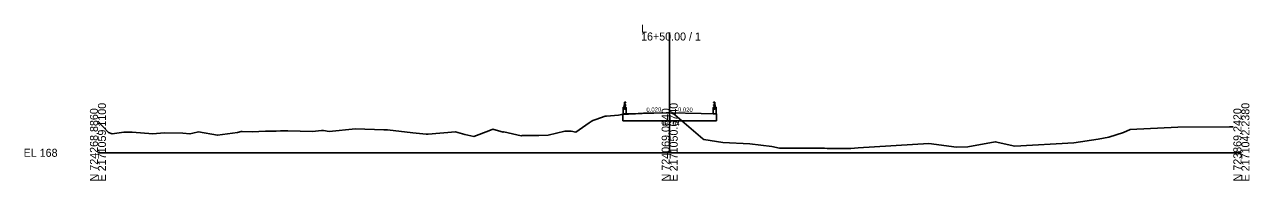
# Model space of a CAD drawing. Extents: x -26 to 2803, y -10 to 9553.
# Drawn here: x -25.7 to 402.8, y 8990.3 to 9044.9 of the extents above; entities that cross this region are included whole.
import ezdxf

# ---------------------------------------------------------------- set-up
doc = ezdxf.new("R2010")
doc.units = 0
for name, color, linetype in [('Exist Cross Section Cell', 7, 'Continuous'), ('Exist XS Center Line Elevation Label', 7, 'Continuous'), ('Exist XS Ground Line', 7, 'Continuous'), ('Prop XS Bridge', 7, 'Continuous'), ('Prop XS Dump Level', 7, 'Continuous'), ('Prop XS SE Text', 7, 'Continuous')]:
    doc.layers.add(name, color=color, linetype=linetype)

msp = doc.modelspace()

# ---------------------------------------------------------------- linework, layer by layer
at = {"layer": 'Exist Cross Section Cell'}
for p, q in [((200, 9000), (200, 9042.09)), ((0, 9000), (200, 9000)), ((200, 9000), (400, 9000))]:
    msp.add_line(p, q, dxfattribs=at)
at = {"layer": 'Exist XS Ground Line'}
msp.add_lwpolyline([(0, 9011.05), (3.69, 9007.06), (5, 9006.6), (9.03, 9007.27), (11.93, 9007.24), (19.24, 9006.62), (23.12, 9006.96), (29.69, 9006.9), (32.17, 9006.59), (33.16, 9006.86), (35.17, 9007.29), (41.79, 9006.14), (48.79, 9007.15), (50.06, 9007.4), (50.46, 9007.4), (53.98, 9007.38), (58.63, 9007.55), (62.31, 9007.62), (63.91, 9007.64), (65.19, 9007.66), (66.45, 9007.66), (75.05, 9007.43), (78.24, 9007.83), (78.86, 9007.75), (80.84, 9007.43), (90.15, 9008.34), (100, 9008.03), (101.29, 9008.02), (110.11, 9007.03), (114.79, 9006.52), (115.56, 9006.53), (125.09, 9007.31), (128.3, 9006.39), (131.55, 9005.76), (136.72, 9007.69), (138.09, 9008.22), (141.7, 9007.24), (141.97, 9007.29), (148.05, 9005.99), (148.39, 9006.01), (154.22, 9006.08), (157.47, 9006.13), (163.38, 9007.55), (165.56, 9007.54), (167.18, 9007.27), (171.89, 9010.51), (172.54, 9011), (173.13, 9011.25), (174.14, 9011.6), (177.42, 9012.84), (177.85, 9012.81), (182.16, 9013.18), (183.21, 9013.44), (190.4, 9013.78), (190.85, 9013.85), (198.83, 9014.03), (200, 9013.94), (200.81, 9013.88), (201.58, 9013.56), (201.79, 9013.27), (211.57, 9004.94), (211.92, 9004.66), (218.59, 9003.59), (228.02, 9003.15), (235.75, 9002.18), (238.48, 9001.61), (248.27, 9001.62), (254.12, 9001.58), (255.06, 9001.53), (263.38, 9001.47), (265.92, 9001.78), (290.67, 9003.3), (300.31, 9001.96), (304.25, 9002.06), (313.87, 9003.88), (320.71, 9002.37), (341.44, 9003.54), (349.87, 9004.82), (353.68, 9005.47), (358.78, 9007.05), (361.12, 9008.2), (377.78, 9008.97), (395.82, 9009.05), (397.1, 9009.06)], dxfattribs=at)
at = {"layer": 'Prop XS Bridge'}
for p, q in [((184.19, 9017.72), (184.07, 9016)), ((184.19, 9017.72), (184.3, 9017.75)), ((184.19, 9015.96), (184.19, 9017.72)), ((184.19, 9016.9), (184.19, 9016.9)), ((184.37, 9017.75), (184.3, 9017.75)), ((184.3, 9015.96), (184.3, 9017.75)), ((184.37, 9015.96), (184.37, 9017.75)), ((184.43, 9017.72), (184.43, 9017.63)), ((184.43, 9017.53), (184.43, 9017.63)), ((184.43, 9016.79), (184.43, 9016.69)), ((184.43, 9016.59), (184.43, 9016.69)), ((215.57, 9017.72), (215.57, 9017.63)), ((215.57, 9017.53), (215.57, 9017.63)), ((215.57, 9016.79), (215.57, 9016.69)), ((215.57, 9016.59), (215.57, 9016.69)), ((215.63, 9017.75), (215.7, 9017.75)), ((215.63, 9015.96), (215.63, 9017.75)), ((215.81, 9017.72), (215.7, 9017.75)), ((215.7, 9015.96), (215.7, 9017.75)), ((215.81, 9015.96), (215.81, 9017.72)), ((215.81, 9017.72), (215.93, 9016)), ((215.81, 9016.9), (215.81, 9016.9)), ((183.57, 9013.6), (183.62, 9013.66)), ((183.57, 9013.6), (183.57, 9011.15)), ((183.7, 9013.66), (183.62, 9013.66)), ((183.69, 9015.88), (183.73, 9015.93)), ((183.69, 9015.88), (183.69, 9013.66)), ((184.75, 9013.66), (183.7, 9013.66)), ((184.7, 9015.93), (183.73, 9015.93)), ((184.07, 9016.02), (184.07, 9016.05)), ((184.07, 9015.96), (184.07, 9016)), ((184.2, 9015.89), (184.11, 9015.89)), ((184.2, 9015.88), (184.11, 9015.88)), ((184.15, 9015.85), (184.11, 9015.85)), ((184.15, 9015.84), (184.11, 9015.84)), ((184.15, 9015.81), (184.11, 9015.81)), ((184.15, 9015.8), (184.11, 9015.8)), ((184.15, 9015.77), (184.11, 9015.77)), ((184.15, 9015.76), (184.11, 9015.76)), ((184.15, 9015.73), (184.11, 9015.73)), ((184.15, 9015.72), (184.11, 9015.72)), ((184.15, 9015.87), (184.13, 9015.87)), ((184.15, 9015.86), (184.13, 9015.86)), ((184.15, 9015.83), (184.13, 9015.83)), ((184.15, 9015.82), (184.13, 9015.82)), ((184.15, 9015.79), (184.13, 9015.79)), ((184.15, 9015.78), (184.13, 9015.78)), ((184.15, 9015.75), (184.13, 9015.75)), ((184.15, 9015.74), (184.13, 9015.74)), ((184.18, 9016.04), (184.14, 9016.04)), ((184.14, 9016.04), (184.14, 9016)), ((184.14, 9015.89), (184.14, 9015.96)), ((184.16, 9015.87), (184.15, 9015.87)), ((184.15, 9015.87), (184.15, 9015.37)), ((184.18, 9015.87), (184.16, 9015.87)), ((184.16, 9015.87), (184.16, 9015.37)), ((184.18, 9015.86), (184.16, 9015.86)), ((184.2, 9015.85), (184.16, 9015.85)), ((184.2, 9015.84), (184.16, 9015.84)), ((184.18, 9015.83), (184.16, 9015.83)), ((184.18, 9015.82), (184.16, 9015.82)), ((184.2, 9015.81), (184.16, 9015.81)), ((184.2, 9015.8), (184.16, 9015.8)), ((184.18, 9015.79), (184.16, 9015.79)), ((184.18, 9015.78), (184.16, 9015.78)), ((184.2, 9015.77), (184.16, 9015.77)), ((184.2, 9015.76), (184.16, 9015.76)), ((184.18, 9015.75), (184.16, 9015.75)), ((184.18, 9015.74), (184.16, 9015.74)), ((184.2, 9015.73), (184.16, 9015.73)), ((184.2, 9015.72), (184.16, 9015.72)), ((184.18, 9016), (184.18, 9016.04)), ((184.18, 9015.89), (184.18, 9015.96)), ((184.43, 9015.32), (184.21, 9015.32)), ((184.43, 9015.3), (184.21, 9015.3)), ((184.53, 9015.89), (184.44, 9015.89)), ((184.53, 9015.88), (184.44, 9015.88)), ((184.48, 9015.85), (184.44, 9015.85)), ((184.48, 9015.84), (184.44, 9015.84)), ((184.48, 9015.81), (184.44, 9015.81)), ((184.48, 9015.8), (184.44, 9015.8)), ((184.48, 9015.77), (184.44, 9015.77)), ((184.48, 9015.76), (184.44, 9015.76)), ((184.48, 9015.73), (184.44, 9015.73)), ((184.48, 9015.72), (184.44, 9015.72)), ((184.48, 9015.87), (184.46, 9015.87)), ((184.48, 9015.86), (184.46, 9015.86)), ((184.48, 9015.83), (184.46, 9015.83)), ((184.48, 9015.82), (184.46, 9015.82)), ((184.48, 9015.79), (184.46, 9015.79)), ((184.48, 9015.78), (184.46, 9015.78)), ((184.48, 9015.75), (184.46, 9015.75)), ((184.48, 9015.74), (184.46, 9015.74)), ((184.51, 9016.05), (184.47, 9016.05)), ((184.47, 9016.05), (184.47, 9016.01)), ((184.47, 9015.89), (184.47, 9015.97)), ((184.49, 9015.87), (184.48, 9015.87)), ((184.48, 9015.87), (184.48, 9015.37)), ((184.51, 9015.87), (184.49, 9015.87)), ((184.49, 9015.87), (184.49, 9015.37)), ((184.51, 9015.86), (184.49, 9015.86)), ((184.53, 9015.85), (184.49, 9015.85)), ((184.53, 9015.84), (184.49, 9015.84)), ((184.51, 9015.83), (184.49, 9015.83)), ((184.51, 9015.82), (184.49, 9015.82)), ((184.53, 9015.81), (184.49, 9015.81)), ((184.53, 9015.8), (184.49, 9015.8)), ((184.51, 9015.79), (184.49, 9015.79)), ((184.51, 9015.78), (184.49, 9015.78)), ((184.53, 9015.77), (184.49, 9015.77)), ((184.53, 9015.76), (184.49, 9015.76)), ((184.51, 9015.75), (184.49, 9015.75)), ((184.51, 9015.74), (184.49, 9015.74)), ((184.53, 9015.73), (184.49, 9015.73)), ((184.53, 9015.72), (184.49, 9015.72)), ((184.51, 9016.01), (184.51, 9016.05)), ((184.51, 9015.89), (184.51, 9015.97)), ((184.7, 9015.93), (184.75, 9015.88)), ((184.75, 9015.88), (184.75, 9013.66)), ((189, 9013.74), (184.75, 9013.66)), ((189, 9013.74), (200, 9013.96)), ((200, 9013.96), (211, 9013.74)), ((211, 9013.74), (215.25, 9013.66)), ((215.25, 9015.88), (215.3, 9015.93)), ((215.25, 9015.88), (215.25, 9013.66)), ((215.25, 9013.66), (216.3, 9013.66)), ((215.3, 9015.93), (216.27, 9015.93)), ((215.47, 9015.89), (215.56, 9015.89)), ((215.47, 9015.88), (215.56, 9015.88)), ((215.47, 9015.85), (215.51, 9015.85)), ((215.47, 9015.84), (215.51, 9015.84)), ((215.47, 9015.81), (215.51, 9015.81)), ((215.47, 9015.8), (215.51, 9015.8)), ((215.47, 9015.77), (215.51, 9015.77)), ((215.47, 9015.76), (215.51, 9015.76)), ((215.47, 9015.73), (215.51, 9015.73)), ((215.47, 9015.72), (215.51, 9015.72)), ((215.49, 9016.01), (215.49, 9016.05)), ((215.49, 9016.05), (215.53, 9016.05)), ((215.49, 9015.89), (215.49, 9015.97)), ((215.49, 9015.87), (215.51, 9015.87)), ((215.49, 9015.86), (215.51, 9015.86)), ((215.49, 9015.83), (215.51, 9015.83)), ((215.49, 9015.82), (215.51, 9015.82)), ((215.49, 9015.79), (215.51, 9015.79)), ((215.49, 9015.78), (215.51, 9015.78)), ((215.49, 9015.75), (215.51, 9015.75)), ((215.49, 9015.74), (215.51, 9015.74)), ((215.51, 9015.87), (215.52, 9015.87)), ((215.51, 9015.87), (215.51, 9015.37)), ((215.52, 9015.87), (215.54, 9015.87)), ((215.52, 9015.87), (215.52, 9015.37)), ((215.52, 9015.86), (215.54, 9015.86)), ((215.52, 9015.85), (215.56, 9015.85)), ((215.52, 9015.84), (215.56, 9015.84)), ((215.52, 9015.83), (215.54, 9015.83)), ((215.52, 9015.82), (215.54, 9015.82)), ((215.52, 9015.81), (215.56, 9015.81)), ((215.52, 9015.8), (215.56, 9015.8)), ((215.52, 9015.79), (215.54, 9015.79)), ((215.52, 9015.78), (215.54, 9015.78)), ((215.52, 9015.77), (215.56, 9015.77)), ((215.52, 9015.76), (215.56, 9015.76)), ((215.52, 9015.75), (215.54, 9015.75)), ((215.52, 9015.74), (215.54, 9015.74)), ((215.52, 9015.73), (215.56, 9015.73)), ((215.52, 9015.72), (215.56, 9015.72)), ((215.53, 9016.05), (215.53, 9016.01)), ((215.53, 9015.89), (215.53, 9015.97)), ((215.57, 9015.32), (215.79, 9015.32)), ((215.57, 9015.3), (215.79, 9015.3)), ((215.8, 9015.89), (215.89, 9015.89)), ((215.8, 9015.88), (215.89, 9015.88)), ((215.8, 9015.85), (215.84, 9015.85)), ((215.8, 9015.84), (215.84, 9015.84)), ((215.8, 9015.81), (215.84, 9015.81)), ((215.8, 9015.8), (215.84, 9015.8)), ((215.8, 9015.77), (215.84, 9015.77)), ((215.8, 9015.76), (215.84, 9015.76)), ((215.8, 9015.73), (215.84, 9015.73)), ((215.8, 9015.72), (215.84, 9015.72)), ((215.82, 9016), (215.82, 9016.04)), ((215.82, 9016.04), (215.86, 9016.04)), ((215.82, 9015.89), (215.82, 9015.96)), ((215.82, 9015.87), (215.84, 9015.87)), ((215.82, 9015.86), (215.84, 9015.86)), ((215.82, 9015.83), (215.84, 9015.83)), ((215.82, 9015.82), (215.84, 9015.82)), ((215.82, 9015.79), (215.84, 9015.79)), ((215.82, 9015.78), (215.84, 9015.78)), ((215.82, 9015.75), (215.84, 9015.75)), ((215.82, 9015.74), (215.84, 9015.74)), ((215.84, 9015.87), (215.85, 9015.87)), ((215.84, 9015.87), (215.84, 9015.37)), ((215.85, 9015.87), (215.87, 9015.87)), ((215.85, 9015.87), (215.85, 9015.37)), ((215.85, 9015.86), (215.87, 9015.86)), ((215.85, 9015.85), (215.89, 9015.85)), ((215.85, 9015.84), (215.89, 9015.84)), ((215.85, 9015.83), (215.87, 9015.83)), ((215.85, 9015.82), (215.87, 9015.82)), ((215.85, 9015.81), (215.89, 9015.81)), ((215.85, 9015.8), (215.89, 9015.8)), ((215.85, 9015.79), (215.87, 9015.79)), ((215.85, 9015.78), (215.87, 9015.78)), ((215.85, 9015.77), (215.89, 9015.77)), ((215.85, 9015.76), (215.89, 9015.76)), ((215.85, 9015.75), (215.87, 9015.75)), ((215.85, 9015.74), (215.87, 9015.74)), ((215.85, 9015.73), (215.89, 9015.73)), ((215.85, 9015.72), (215.89, 9015.72)), ((215.86, 9016.04), (215.86, 9016)), ((215.86, 9015.89), (215.86, 9015.96)), ((215.93, 9016.02), (215.93, 9016.05)), ((215.93, 9015.96), (215.93, 9016)), ((216.27, 9015.93), (216.31, 9015.88)), ((216.3, 9013.66), (216.38, 9013.66)), ((216.31, 9015.88), (216.31, 9013.66)), ((216.43, 9013.6), (216.38, 9013.66)), ((216.43, 9013.6), (216.43, 9011.15)), ((216.43, 9011.15), (183.57, 9011.15))]:
    msp.add_line(p, q, dxfattribs=at)
for points in [[(184.55, 9015.93), (184.55, 9015.97), (184.39, 9015.97), (184.39, 9016.34), (184.37, 9016.34), (184.37, 9015.96), (184.07, 9015.96), (184.07, 9015.99), (184.07, 9015.99), (184.07, 9015.93), (184.21, 9015.93), (184.21, 9015.95), (184.35, 9015.95), (184.35, 9015.93), (184.55, 9015.93)], [(184.37, 9017.5), (184.37, 9017.55), (184.39, 9017.55), (184.39, 9017.54), (184.39, 9017.54), (184.39, 9017.52), (184.42, 9017.52), (184.42, 9017.55), (184.42, 9017.63), (184.42, 9017.7), (184.42, 9017.73), (184.39, 9017.73), (184.39, 9017.71), (184.39, 9017.71), (184.39, 9017.7), (184.37, 9017.7), (184.37, 9017.75)], [(184.37, 9016.57), (184.37, 9016.61), (184.39, 9016.61), (184.39, 9016.6), (184.39, 9016.6), (184.39, 9016.58), (184.42, 9016.58), (184.42, 9016.61), (184.42, 9016.69), (184.42, 9016.76), (184.42, 9016.79), (184.39, 9016.79), (184.39, 9016.77), (184.39, 9016.77), (184.39, 9016.77), (184.37, 9016.77), (184.37, 9016.81)], [(215.45, 9015.93), (215.45, 9015.97), (215.61, 9015.97), (215.61, 9016.34), (215.63, 9016.34), (215.63, 9015.96), (215.93, 9015.96), (215.93, 9015.99), (215.93, 9015.99), (215.93, 9015.93), (215.79, 9015.93), (215.79, 9015.95), (215.65, 9015.95), (215.65, 9015.93), (215.45, 9015.93)], [(215.63, 9017.5), (215.63, 9017.55), (215.61, 9017.55), (215.61, 9017.54), (215.61, 9017.54), (215.61, 9017.52), (215.58, 9017.52), (215.58, 9017.55), (215.58, 9017.63), (215.58, 9017.7), (215.58, 9017.73), (215.61, 9017.73), (215.61, 9017.71), (215.61, 9017.71), (215.61, 9017.7), (215.63, 9017.7), (215.63, 9017.75)], [(215.63, 9016.57), (215.63, 9016.61), (215.61, 9016.61), (215.61, 9016.6), (215.61, 9016.6), (215.61, 9016.58), (215.58, 9016.58), (215.58, 9016.61), (215.58, 9016.69), (215.58, 9016.76), (215.58, 9016.79), (215.61, 9016.79), (215.61, 9016.77), (215.61, 9016.77), (215.61, 9016.77), (215.63, 9016.77), (215.63, 9016.81)], [(184.11, 9015.89), (184.11, 9015.88), (184.13, 9015.87), (184.13, 9015.86), (184.11, 9015.85), (184.11, 9015.84), (184.13, 9015.83), (184.13, 9015.82), (184.11, 9015.81), (184.11, 9015.8), (184.13, 9015.79), (184.13, 9015.78), (184.11, 9015.77), (184.11, 9015.76), (184.13, 9015.75), (184.13, 9015.74), (184.11, 9015.73), (184.11, 9015.72)], [(184.2, 9015.96), (184.2, 9015.97), (184.16, 9015.97), (184.12, 9015.97), (184.12, 9015.96)], [(184.19, 9015.97), (184.19, 9016), (184.18, 9016), (184.13, 9016), (184.13, 9016), (184.13, 9015.97), (184.19, 9015.97), (184.17, 9015.97), (184.17, 9016), (184.17, 9016), (184.17, 9016), (184.16, 9016), (184.15, 9016), (184.15, 9016), (184.15, 9015.97), (184.15, 9016), (184.14, 9016)], [(184.2, 9015.89), (184.2, 9015.88), (184.18, 9015.87), (184.18, 9015.86), (184.2, 9015.85), (184.2, 9015.84), (184.18, 9015.83), (184.18, 9015.82), (184.2, 9015.81), (184.2, 9015.8), (184.18, 9015.79), (184.18, 9015.78), (184.2, 9015.77), (184.2, 9015.76), (184.18, 9015.75), (184.18, 9015.74), (184.2, 9015.73), (184.2, 9015.72)], [(184.44, 9015.89), (184.44, 9015.88), (184.46, 9015.87), (184.46, 9015.86), (184.44, 9015.85), (184.44, 9015.84), (184.46, 9015.83), (184.46, 9015.82), (184.44, 9015.81), (184.44, 9015.8), (184.46, 9015.79), (184.46, 9015.78), (184.44, 9015.77), (184.44, 9015.76), (184.46, 9015.75), (184.46, 9015.74), (184.44, 9015.73), (184.44, 9015.72)], [(184.53, 9015.97), (184.53, 9015.98), (184.49, 9015.98), (184.45, 9015.98), (184.45, 9015.97)], [(184.52, 9015.98), (184.52, 9016.01), (184.51, 9016.01), (184.46, 9016.01), (184.46, 9016.01), (184.46, 9015.98), (184.52, 9015.98), (184.5, 9015.98), (184.5, 9016.01), (184.5, 9016.01), (184.5, 9016.01), (184.49, 9016.01), (184.48, 9016.01), (184.48, 9016.01), (184.48, 9015.98), (184.48, 9016.01), (184.47, 9016.01)], [(184.53, 9015.89), (184.53, 9015.88), (184.51, 9015.87), (184.51, 9015.86), (184.53, 9015.85), (184.53, 9015.84), (184.51, 9015.83), (184.51, 9015.82), (184.53, 9015.81), (184.53, 9015.8), (184.51, 9015.79), (184.51, 9015.78), (184.53, 9015.77), (184.53, 9015.76), (184.51, 9015.75), (184.51, 9015.74), (184.53, 9015.73), (184.53, 9015.72)], [(215.47, 9015.97), (215.47, 9015.98), (215.51, 9015.98), (215.55, 9015.98), (215.55, 9015.97)], [(215.47, 9015.89), (215.47, 9015.88), (215.49, 9015.87), (215.49, 9015.86), (215.47, 9015.85), (215.47, 9015.84), (215.49, 9015.83), (215.49, 9015.82), (215.47, 9015.81), (215.47, 9015.8), (215.49, 9015.79), (215.49, 9015.78), (215.47, 9015.77), (215.47, 9015.76), (215.49, 9015.75), (215.49, 9015.74), (215.47, 9015.73), (215.47, 9015.72)], [(215.48, 9015.98), (215.48, 9016.01), (215.49, 9016.01), (215.54, 9016.01), (215.54, 9016.01), (215.54, 9015.98), (215.48, 9015.98), (215.5, 9015.98), (215.5, 9016.01), (215.5, 9016.01), (215.5, 9016.01), (215.51, 9016.01), (215.52, 9016.01), (215.52, 9016.01), (215.52, 9015.98), (215.52, 9016.01), (215.53, 9016.01)], [(215.56, 9015.89), (215.56, 9015.88), (215.54, 9015.87), (215.54, 9015.86), (215.56, 9015.85), (215.56, 9015.84), (215.54, 9015.83), (215.54, 9015.82), (215.56, 9015.81), (215.56, 9015.8), (215.54, 9015.79), (215.54, 9015.78), (215.56, 9015.77), (215.56, 9015.76), (215.54, 9015.75), (215.54, 9015.74), (215.56, 9015.73), (215.56, 9015.72)], [(215.8, 9015.96), (215.8, 9015.97), (215.84, 9015.97), (215.88, 9015.97), (215.88, 9015.96)], [(215.8, 9015.89), (215.8, 9015.88), (215.82, 9015.87), (215.82, 9015.86), (215.8, 9015.85), (215.8, 9015.84), (215.82, 9015.83), (215.82, 9015.82), (215.8, 9015.81), (215.8, 9015.8), (215.82, 9015.79), (215.82, 9015.78), (215.8, 9015.77), (215.8, 9015.76), (215.82, 9015.75), (215.82, 9015.74), (215.8, 9015.73), (215.8, 9015.72)], [(215.81, 9015.97), (215.81, 9016), (215.82, 9016), (215.87, 9016), (215.87, 9016), (215.87, 9015.97), (215.81, 9015.97), (215.83, 9015.97), (215.83, 9016), (215.83, 9016), (215.83, 9016), (215.84, 9016), (215.85, 9016), (215.85, 9016), (215.85, 9015.97), (215.85, 9016), (215.86, 9016)], [(215.89, 9015.89), (215.89, 9015.88), (215.87, 9015.87), (215.87, 9015.86), (215.89, 9015.85), (215.89, 9015.84), (215.87, 9015.83), (215.87, 9015.82), (215.89, 9015.81), (215.89, 9015.8), (215.87, 9015.79), (215.87, 9015.78), (215.89, 9015.77), (215.89, 9015.76), (215.87, 9015.75), (215.87, 9015.74), (215.89, 9015.73), (215.89, 9015.72)]]:
    msp.add_lwpolyline(points, dxfattribs=at)
for centre in [(184.12, 9015.74), (184.53, 9015.74), (215.47, 9015.74), (215.88, 9015.74)]:
    msp.add_circle(centre, 0.00793, dxfattribs=at)
for centre, radius, start, end in [((184.44, 9017.72), 0.00744, 90, 180), ((184.44, 9017.53), 0.00744, 180, 270), ((184.44, 9016.79), 0.00744, 90, 180), ((184.44, 9016.59), 0.00744, 180, 270), ((215.56, 9017.72), 0.00744, 0, 90), ((215.56, 9017.53), 0.00744, 270, 360), ((215.56, 9016.79), 0.00744, 0, 90), ((215.56, 9016.59), 0.00744, 270, 360), ((184.21, 9015.37), 0.0665, 180, 270), ((184.21, 9015.37), 0.0507, 180, 270), ((184.43, 9015.37), 0.0507, 270, 0), ((184.43, 9015.37), 0.0665, 270, 0), ((215.57, 9015.37), 0.0665, 180, 270), ((215.57, 9015.37), 0.0507, 180, 270), ((215.79, 9015.37), 0.0507, 270, 0), ((215.79, 9015.37), 0.0665, 270, 0)]:
    msp.add_arc(centre, radius, start, end, dxfattribs=at)
for centre, major_axis, ratio, start_param, end_param in [((184.37, 9017.63), (0.318, 0), 0.39036, 6.282787, 7.853967), ((184.37, 9017.63), (0.318, 0), 0.39036, 4.712404, 6.282787), ((184.37, 9016.69), (0.318, 0), 0.39036, 6.282787, 7.853967), ((184.37, 9016.69), (0.318, 0), 0.39036, 4.712404, 6.282787), ((184.44, 9017.63), (0.211, 0), 0.495501, 6.282718, 7.853881), ((184.44, 9017.63), (0.211, 0), 0.495501, 4.712489, 6.282718), ((184.44, 9016.69), (0.211, 0), 0.495501, 6.282718, 7.853881), ((184.44, 9016.69), (0.211, 0), 0.495501, 4.712489, 6.282718), ((215.63, 9017.63), (-0.318, 0), 0.39036, 4.712404, 6.283584), ((215.63, 9017.63), (-0.318, 0), 0.39036, 0.000398, 1.570782), ((215.63, 9016.69), (-0.318, 0), 0.39036, 4.712404, 6.283584), ((215.63, 9016.69), (-0.318, 0), 0.39036, 0.000398, 1.570782), ((215.56, 9017.63), (-0.211, 0), 0.495501, 4.712489, 6.283652), ((215.56, 9017.63), (-0.211, 0), 0.495501, 0.000467, 1.570696), ((215.56, 9016.69), (-0.211, 0), 0.495501, 4.712489, 6.283652), ((215.56, 9016.69), (-0.211, 0), 0.495501, 0.000467, 1.570696)]:
    msp.add_ellipse(centre, major_axis=major_axis, ratio=ratio, start_param=start_param, end_param=end_param, dxfattribs=at)
at = {"layer": 'Prop XS Dump Level'}
for p, q in [((189, 9013.74), (200, 9013.96)), ((200, 9013.96), (211, 9013.74))]:
    msp.add_line(p, q, dxfattribs=at)

# ---------------------------------------------------------------- texts
at = {"layer": 'Exist Cross Section Cell'}
for s, p in [('16+50.00 / 1', (190, 9039.29)), ('L', (190, 9042.09)), ('EL 168', (-26, 8998.6))]:
    msp.add_text(s, height=2.8, dxfattribs=at).set_placement(p)
for s, p in [('E 2171059.1100', (2.8, 8990)), ('E 2171050.6740', (202.8, 8990)), ('E 2171042.2380', (402.8, 8990)), ('N 724268.8860', (0, 8990)), ('N 724069.0640', (200, 8990)), ('N 723869.2420', (400, 8990))]:
    msp.add_text(s, height=2.8, rotation=90, dxfattribs=at).set_placement(p)
at = {"layer": 'Exist XS Center Line Elevation Label'}
msp.add_text('181.94', height=1.5, dxfattribs=at).set_placement((197.15, 9009.44))
at = {"layer": 'Prop XS SE Text'}
for rotation, p in [(1.1458, (191.88, 9014.3)), (358.8542, (202.88, 9014.4))]:
    msp.add_text('0.020', height=1.5, rotation=rotation, dxfattribs=at).set_placement(p)

doc.saveas('drawing.dxf')
